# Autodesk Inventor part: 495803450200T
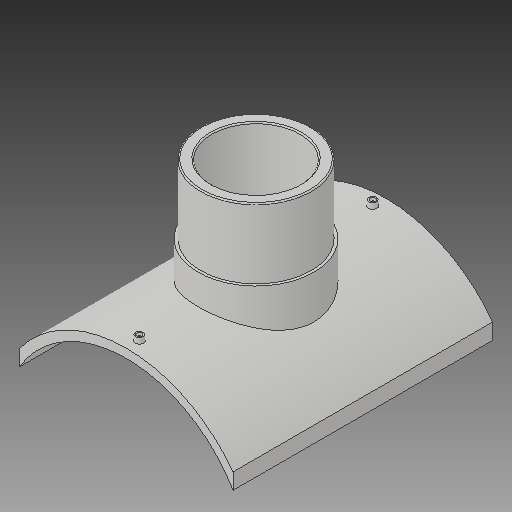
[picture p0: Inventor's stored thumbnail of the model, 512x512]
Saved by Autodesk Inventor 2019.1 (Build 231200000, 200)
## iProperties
Created: 2017-10
Part Number: 495803450200T
Material: Generic
Description: PLASSON BRANCH SADDLE  450x200
Document SubType Name: Modeling
Designer: KIM
Mass: 2754.05 g
Surface Area: 3037.44 cm^2
Volume: 2754.05 cm^3
Density: 1 g/cm^3
Appearance: Default
Author: KIM
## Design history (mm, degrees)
derived "495803.ipt"
feature "Solid1::495803.ipt"
tag "TaggingFeature1"
body "Solid1"
other parameters: "d1" = 16, "d2" = 387, "d4" = 0, "d12" = 250.6, "d13" = 14, "d14" = 211.5, "d16" = 5 deg, "d18" = 4, "d19" = 14, "d20" = 0, "d21" = 3, "d22" = 0, "d23" = 421, "d25" = 16, "d28" = 0, "d29" = 9.6, "d31" = 0, "d33" = 0, "d34" = 4.5, "d37" = 126, "d38" = 0, "d39" = 2.25, "B_" = 387, "x_" = 16, "D_" = 16
